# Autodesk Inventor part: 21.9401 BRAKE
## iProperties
Created: 2010-10
Part Number: 21.9401 BRAKE
Document SubType Name: Modeling
Designer: Administrator
Density: 1.4 g/cm^3
Material: PVC-U
Mass: 27.9567 g
Surface Area: 97.5019 cm^2
Volume: 19.969 cm^3
Author: Administrator
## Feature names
1. Base1
